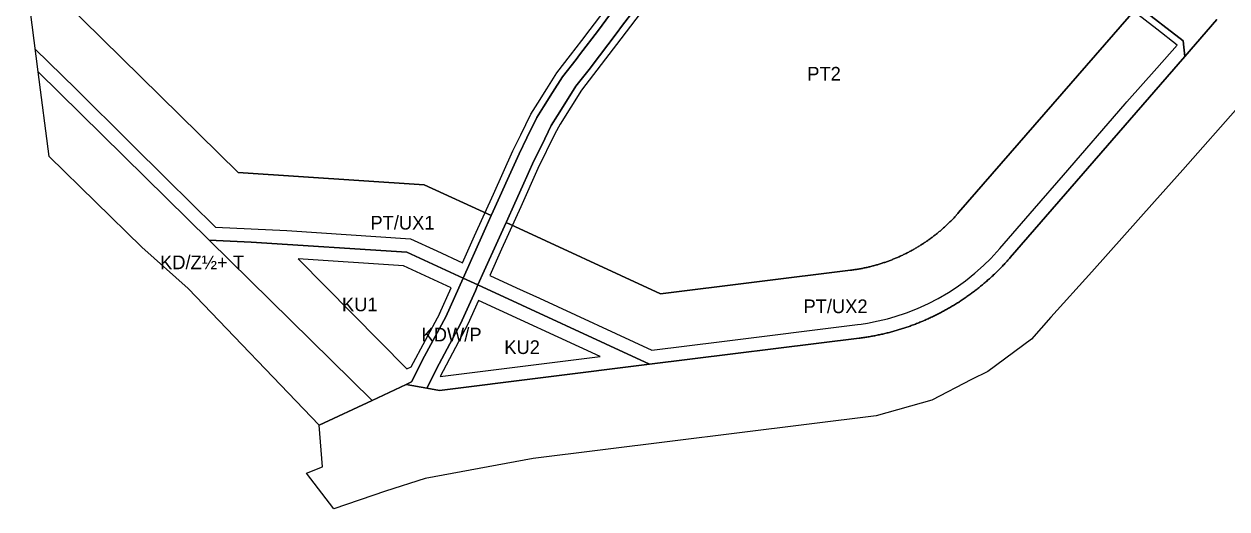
# Model space of a CAD drawing. Extents: x -297746 to -295403, y 27112 to 28877.
# Drawn here: x -297536 to -296657, y 27112 to 27466 of the extents above; entities that cross this region are included whole.
import ezdxf

# ---------------------------------------------------------------- set-up
doc = ezdxf.new("R2010")
doc.units = 0
for name, color, linetype in [('linie_rozgraniczajace', 7, 'Continuous'), ('linie_zabudowy_nieprzekraczalne', 7, 'Continuous'), ('linie_zabudowy_obowiazujace', 7, 'Continuous'), ('oznaczenia_przeznaczen', 7, 'Continuous')]:
    doc.layers.add(name, color=color, linetype=linetype)

msp = doc.modelspace()

# ---------------------------------------------------------------- linework, layer by layer
at = {"layer": 'linie_rozgraniczajace'}
for points in [[(-297194.759, 27325.796), (-297243.742, 27348.41), (-297379.62, 27357.248), (-297536.097, 27511.179)], [(-296721.993, 27478.885), (-296853.18, 27327.985), (-296853.646, 27327.453), (-296854.114, 27326.923), (-296854.585, 27326.396), (-296855.06, 27325.872), (-296855.537, 27325.35), (-296856.018, 27324.831), (-296856.501, 27324.315), (-296856.987, 27323.802), (-296857.476, 27323.291), (-296857.968, 27322.783), (-296858.463, 27322.278), (-296858.96, 27321.776), (-296859.461, 27321.276), (-296859.964, 27320.779), (-296860.47, 27320.285), (-296860.979, 27319.795), (-296861.491, 27319.306), (-296862.005, 27318.821), (-296862.522, 27318.339), (-296863.042, 27317.86), (-296863.565, 27317.383), (-296864.09, 27316.91), (-296864.618, 27316.439), (-296865.148, 27315.972), (-296865.682, 27315.508), (-296866.217, 27315.046), (-296866.756, 27314.588), (-296867.297, 27314.133), (-296867.84, 27313.68), (-296868.386, 27313.231), (-296868.935, 27312.785), (-296869.486, 27312.342), (-296870.04, 27311.902), (-296870.596, 27311.466), (-296871.155, 27311.032), (-296871.716, 27310.602), (-296872.279, 27310.174), (-296872.845, 27309.75), (-296873.413, 27309.33), (-296873.984, 27308.912), (-296874.557, 27308.498), (-296875.132, 27308.087), (-296875.71, 27307.679), (-296876.29, 27307.274), (-296876.872, 27306.873), (-296877.457, 27306.475), (-296878.043, 27306.08), (-296878.632, 27305.689), (-296879.224, 27305.301), (-296879.817, 27304.916), (-296880.412, 27304.535), (-296881.01, 27304.157), (-296881.61, 27303.783), (-296882.212, 27303.412), (-296882.816, 27303.044), (-296883.422, 27302.68), (-296884.03, 27302.319), (-296884.64, 27301.961), (-296885.252, 27301.607), (-296885.866, 27301.257), (-296886.482, 27300.91), (-296887.1, 27300.567), (-296887.72, 27300.227)], [(-296872.279, 27310.174), (-296871.716, 27310.602), (-296871.155, 27311.032), (-296870.596, 27311.466), (-296870.04, 27311.902), (-296869.486, 27312.342), (-296868.935, 27312.785), (-296868.386, 27313.231), (-296867.84, 27313.68), (-296867.297, 27314.133), (-296866.756, 27314.588), (-296866.217, 27315.046), (-296865.682, 27315.508), (-296865.148, 27315.972), (-296864.618, 27316.439), (-296864.09, 27316.91), (-296863.565, 27317.383), (-296863.042, 27317.86), (-296862.522, 27318.339), (-296862.005, 27318.821), (-296861.491, 27319.306), (-296860.979, 27319.795), (-296860.47, 27320.285), (-296859.964, 27320.779), (-296859.461, 27321.276), (-296858.96, 27321.776), (-296858.463, 27322.278), (-296857.968, 27322.783), (-296857.476, 27323.291), (-296856.987, 27323.802), (-296856.501, 27324.315), (-296856.018, 27324.831), (-296855.537, 27325.35), (-296855.06, 27325.872), (-296854.585, 27326.396), (-296854.114, 27326.923), (-296853.646, 27327.453), (-296853.18, 27327.985), (-296721.993, 27478.885), (-296689.133, 27453.416), (-296687.895, 27441.898), (-296815.446, 27295.181), (-296815.997, 27294.551), (-296816.55, 27293.923), (-296817.107, 27293.298), (-296817.666, 27292.676), (-296818.228, 27292.057), (-296818.794, 27291.44), (-296819.362, 27290.826), (-296819.933, 27290.215), (-296820.507, 27289.606), (-296821.084, 27289), (-296821.664, 27288.397), (-296822.247, 27287.797), (-296822.833, 27287.199), (-296823.421, 27286.605), (-296824.013, 27286.013), (-296824.607, 27285.424), (-296825.204, 27284.838), (-296825.803, 27284.254), (-296826.406, 27283.674), (-296827.011, 27283.096), (-296827.619, 27282.522), (-296828.23, 27281.95), (-296828.844, 27281.381), (-296829.46, 27280.815), (-296830.079, 27280.252), (-296830.701, 27279.692), (-296831.325, 27279.135), (-296831.952, 27278.581), (-296832.582, 27278.03), (-296833.214, 27277.482), (-296833.849, 27276.937), (-296834.486, 27276.395), (-296835.126, 27275.857), (-296835.769, 27275.321), (-296836.414, 27274.788), (-296837.062, 27274.258), (-296837.712, 27273.732), (-296838.364, 27273.208), (-296839.02, 27272.688), (-296839.677, 27272.171), (-296840.338, 27271.657), (-296841, 27271.146), (-296841.665, 27270.639), (-296842.333, 27270.134), (-296843.003, 27269.633), (-296843.675, 27269.135), (-296844.349, 27268.64), (-296845.026, 27268.148), (-296845.706, 27267.66), (-296846.387, 27267.175), (-296847.071, 27266.693), (-296847.758, 27266.214), (-296848.446, 27265.739), (-296849.137, 27265.267), (-296849.83, 27264.799), (-296850.525, 27264.333), (-296851.223, 27263.871), (-296851.923, 27263.412)], [(-296664.406, 27468.917), (-296687.895, 27441.898), (-296689.133, 27453.416), (-296721.993, 27478.885)], [(-297204.419, 27275.185), (-297215.315, 27280.215), (-297200.803, 27312.318), (-297194.759, 27325.796), (-297194.532, 27326.301), (-297188.463, 27339.812), (-297182.789, 27352.244), (-297174.341, 27371.048), (-297168.583, 27382.582), (-297161.403, 27397.443), (-297156.407, 27405.272), (-297149.85, 27415.719), (-297142.603, 27427.173), (-297132.752, 27439.87), (-297130.244, 27443.163), (-297116.362, 27461.318), (-297108.268, 27472.193)], [(-297088.887, 27477.865), (-297098.677, 27464.98), (-297103.486, 27458.519), (-297115.701, 27442.453), (-297123.238, 27432.557), (-297132.769, 27420.271), (-297139.698, 27409.321), (-297146.268, 27398.854), (-297150.906, 27391.585), (-297157.812, 27377.292), (-297163.495, 27365.907), (-297171.858, 27347.294), (-297177.532, 27334.862), (-297183.585, 27321.387), (-297183.863, 27320.766), (-297189.862, 27307.391), (-297199.748, 27285.531), (-297204.419, 27275.185)], [(-297071.036, 27268.678), (-297183.863, 27320.766), (-297183.585, 27321.387), (-297177.532, 27334.862), (-297171.858, 27347.294), (-297163.495, 27365.907), (-297157.812, 27377.292), (-297150.906, 27391.585), (-297146.268, 27398.854), (-297139.698, 27409.321), (-297132.769, 27420.271), (-297123.238, 27432.557), (-297115.701, 27442.453), (-297103.486, 27458.519), (-297098.677, 27464.98), (-297088.887, 27477.865)], [(-297108.268, 27472.193), (-297116.362, 27461.318), (-297130.244, 27443.163), (-297132.752, 27439.87), (-297142.603, 27427.173), (-297149.85, 27415.719), (-297156.407, 27405.272), (-297161.403, 27397.443), (-297168.583, 27382.582)], [(-296855.454, 27261.169), (-296854.743, 27261.611), (-296854.035, 27262.056), (-296853.329, 27262.505), (-296852.625, 27262.957), (-296851.923, 27263.412), (-296851.223, 27263.871), (-296850.525, 27264.333), (-296849.83, 27264.799), (-296849.137, 27265.267), (-296848.446, 27265.739), (-296847.758, 27266.214), (-296847.071, 27266.693), (-296846.387, 27267.175), (-296845.706, 27267.66), (-296845.026, 27268.148), (-296844.349, 27268.64), (-296843.675, 27269.135), (-296843.003, 27269.633), (-296842.333, 27270.134), (-296841.665, 27270.639), (-296841, 27271.146), (-296840.338, 27271.657), (-296839.677, 27272.171), (-296839.02, 27272.688), (-296838.364, 27273.208), (-296837.712, 27273.732), (-296837.062, 27274.258), (-296836.414, 27274.788), (-296835.769, 27275.321), (-296835.126, 27275.857), (-296834.486, 27276.395), (-296833.849, 27276.937), (-296833.214, 27277.482), (-296832.582, 27278.03), (-296831.952, 27278.581), (-296831.325, 27279.135), (-296830.701, 27279.692), (-296830.079, 27280.252), (-296829.46, 27280.815), (-296828.844, 27281.381), (-296828.23, 27281.95), (-296827.619, 27282.522), (-296827.011, 27283.096), (-296826.406, 27283.674), (-296825.803, 27284.254), (-296825.204, 27284.838), (-296824.607, 27285.424), (-296824.013, 27286.013), (-296823.421, 27286.605), (-296822.833, 27287.199), (-296822.247, 27287.797), (-296821.664, 27288.397), (-296821.084, 27289), (-296820.507, 27289.606), (-296819.933, 27290.215), (-296819.362, 27290.826), (-296818.794, 27291.44), (-296818.228, 27292.057), (-296817.666, 27292.676), (-296817.107, 27293.298), (-296816.55, 27293.923), (-296815.997, 27294.551), (-296815.446, 27295.181), (-296687.895, 27441.898), (-296664.406, 27468.917)], [(-296647.178, 27406.935), (-296689.426, 27359.239), (-296709.944, 27336.075), (-296755.856, 27284.662), (-296785.648, 27251.677), (-296799.802, 27235.521), (-296831.744, 27212.122), (-296843.745, 27206.187), (-296872.727, 27191.091), (-296913.344, 27179.55), (-297163.969, 27148.392), (-297242.956, 27133.917), (-297271.866, 27124.698), (-297309.67, 27111.664)], [(-297168.583, 27382.582), (-297174.341, 27371.048), (-297182.789, 27352.244), (-297188.463, 27339.812), (-297194.532, 27326.301), (-297194.759, 27325.796)], [(-297079.033, 27217.299), (-297204.419, 27275.185), (-297199.748, 27285.531), (-297189.862, 27307.391), (-297183.863, 27320.766), (-297071.036, 27268.678), (-296932.093, 27285.952), (-296931.877, 27285.979), (-296931.176, 27286.07), (-296930.475, 27286.164), (-296929.775, 27286.262), (-296929.075, 27286.365), (-296928.376, 27286.471), (-296927.678, 27286.581), (-296926.98, 27286.695), (-296926.283, 27286.814), (-296925.586, 27286.936), (-296924.891, 27287.062), (-296924.196, 27287.192), (-296923.501, 27287.326), (-296922.808, 27287.463), (-296922.115, 27287.605), (-296921.423, 27287.751), (-296920.732, 27287.9), (-296920.042, 27288.054), (-296919.352, 27288.211), (-296918.664, 27288.372), (-296917.976, 27288.538), (-296917.29, 27288.707), (-296916.604, 27288.879), (-296915.919, 27289.056), (-296915.236, 27289.237), (-296914.553, 27289.421), (-296913.872, 27289.61), (-296913.191, 27289.802), (-296912.512, 27289.998), (-296911.833, 27290.198), (-296911.156, 27290.402), (-296910.48, 27290.609), (-296909.806, 27290.821), (-296909.132, 27291.036), (-296908.46, 27291.255), (-296907.789, 27291.478), (-296907.119, 27291.705), (-296906.45, 27291.935), (-296905.783, 27292.169), (-296905.117, 27292.407), (-296904.453, 27292.649), (-296903.79, 27292.894), (-296903.128, 27293.144), (-296902.468, 27293.396), (-296901.809, 27293.653), (-296901.151, 27293.914), (-296900.495, 27294.178), (-296899.841, 27294.446), (-296899.188, 27294.717), (-296898.537, 27294.992), (-296897.887, 27295.271), (-296897.239, 27295.554), (-296896.592, 27295.84), (-296895.947, 27296.13), (-296895.304, 27296.423), (-296894.662, 27296.721), (-296894.022, 27297.021), (-296893.384, 27297.326), (-296892.748, 27297.634), (-296892.113, 27297.945), (-296891.48, 27298.261), (-296890.849, 27298.579), (-296890.219, 27298.902), (-296889.592, 27299.228), (-296888.966, 27299.557), (-296888.342, 27299.89), (-296887.72, 27300.227), (-296887.1, 27300.567), (-296886.482, 27300.91), (-296885.866, 27301.257), (-296885.252, 27301.607), (-296884.64, 27301.961), (-296884.03, 27302.319), (-296883.422, 27302.68), (-296882.816, 27303.044), (-296882.212, 27303.412), (-296881.61, 27303.783), (-296881.01, 27304.157), (-296880.412, 27304.535), (-296879.817, 27304.916), (-296879.224, 27305.301), (-296878.632, 27305.689), (-296878.043, 27306.08), (-296877.457, 27306.475), (-296876.872, 27306.873), (-296876.29, 27307.274), (-296875.71, 27307.679), (-296875.132, 27308.087), (-296874.557, 27308.498), (-296873.984, 27308.912), (-296873.413, 27309.33), (-296872.845, 27309.75), (-296872.279, 27310.174)], [(-296887.72, 27300.227), (-296888.342, 27299.89), (-296888.966, 27299.557), (-296889.592, 27299.228), (-296890.219, 27298.902), (-296890.849, 27298.579), (-296891.48, 27298.261), (-296892.113, 27297.945), (-296892.748, 27297.634), (-296893.384, 27297.326), (-296894.022, 27297.021), (-296894.662, 27296.721), (-296895.304, 27296.423), (-296895.947, 27296.13), (-296896.592, 27295.84), (-296897.239, 27295.554), (-296897.887, 27295.271), (-296898.537, 27294.992), (-296899.188, 27294.717), (-296899.841, 27294.446), (-296900.495, 27294.178), (-296901.151, 27293.914), (-296901.809, 27293.653), (-296902.468, 27293.396), (-296903.128, 27293.144), (-296903.79, 27292.894), (-296904.453, 27292.649), (-296905.117, 27292.407), (-296905.783, 27292.169), (-296906.45, 27291.935), (-296907.119, 27291.705), (-296907.789, 27291.478), (-296908.46, 27291.255), (-296909.132, 27291.036), (-296909.806, 27290.821), (-296910.48, 27290.609), (-296911.156, 27290.402), (-296911.833, 27290.198), (-296912.512, 27289.998), (-296913.191, 27289.802), (-296913.872, 27289.61), (-296914.553, 27289.421), (-296915.236, 27289.237), (-296915.919, 27289.056), (-296916.604, 27288.879), (-296917.29, 27288.707), (-296917.976, 27288.538), (-296918.664, 27288.372), (-296919.352, 27288.211), (-296920.042, 27288.054), (-296920.732, 27287.9), (-296921.423, 27287.751), (-296922.115, 27287.605), (-296922.808, 27287.463), (-296923.501, 27287.326), (-296924.196, 27287.192), (-296924.891, 27287.062), (-296925.586, 27286.936), (-296926.283, 27286.814), (-296926.98, 27286.695), (-296927.678, 27286.581), (-296928.376, 27286.471), (-296929.075, 27286.365), (-296929.775, 27286.262), (-296930.475, 27286.164), (-296931.176, 27286.07), (-296931.877, 27285.979), (-296932.093, 27285.952), (-297071.036, 27268.678)], [(-297309.67, 27111.664), (-297329.685, 27137.732), (-297317.93, 27142.501), (-297320.472, 27172.702), (-297281.793, 27190.875), (-297256.857, 27202.591), (-297241.827, 27199.879), (-297232.578, 27198.21), (-297079.033, 27217.299), (-296925.925, 27236.334), (-296925.095, 27236.439), (-296924.266, 27236.548), (-296923.437, 27236.662), (-296922.608, 27236.779), (-296921.781, 27236.9), (-296920.953, 27237.025), (-296920.127, 27237.154), (-296919.301, 27237.287), (-296918.475, 27237.423), (-296917.651, 27237.564), (-296916.826, 27237.709), (-296916.003, 27237.858), (-296915.181, 27238.01), (-296914.359, 27238.167), (-296913.538, 27238.327), (-296912.717, 27238.492), (-296911.898, 27238.66), (-296911.079, 27238.832), (-296910.261, 27239.008), (-296909.444, 27239.189), (-296908.628, 27239.373), (-296907.812, 27239.56), (-296906.998, 27239.752), (-296906.185, 27239.948), (-296905.372, 27240.147), (-296904.561, 27240.351), (-296903.75, 27240.558), (-296902.94, 27240.769), (-296902.132, 27240.984), (-296901.324, 27241.203), (-296900.518, 27241.426), (-296899.712, 27241.653), (-296898.908, 27241.883), (-296898.105, 27242.117), (-296897.303, 27242.355), (-296896.502, 27242.597), (-296895.702, 27242.843), (-296894.904, 27243.093), (-296894.106, 27243.346), (-296893.31, 27243.604), (-296892.515, 27243.865), (-296891.722, 27244.129), (-296890.929, 27244.398), (-296890.138, 27244.671), (-296889.349, 27244.947), (-296888.56, 27245.227), (-296887.773, 27245.51), (-296886.987, 27245.798), (-296886.203, 27246.089), (-296885.42, 27246.384), (-296884.639, 27246.683), (-296883.859, 27246.985), (-296883.08, 27247.292), (-296882.303, 27247.602), (-296881.527, 27247.915), (-296880.753, 27248.232), (-296879.98, 27248.553), (-296879.209, 27248.878), (-296878.44, 27249.207), (-296877.672, 27249.539), (-296876.905, 27249.874), (-296876.141, 27250.214), (-296875.378, 27250.557), (-296874.616, 27250.904), (-296873.856, 27251.254), (-296873.098, 27251.608), (-296872.342, 27251.966), (-296871.587, 27252.327), (-296870.834, 27252.692), (-296870.083, 27253.06), (-296869.334, 27253.432), (-296868.586, 27253.807), (-296867.84, 27254.187), (-296867.096, 27254.569), (-296866.354, 27254.956), (-296865.614, 27255.345), (-296864.875, 27255.739), (-296864.139, 27256.136), (-296863.404, 27256.536), (-296862.671, 27256.94), (-296861.941, 27257.347), (-296861.212, 27257.758), (-296860.485, 27258.172), (-296859.76, 27258.59), (-296859.037, 27259.011), (-296858.316, 27259.436), (-296857.598, 27259.864), (-296856.881, 27260.296), (-296856.166, 27260.731), (-296855.454, 27261.169)], [(-296851.923, 27263.412), (-296852.625, 27262.957), (-296853.329, 27262.505), (-296854.035, 27262.056), (-296854.743, 27261.611), (-296855.454, 27261.169), (-296856.166, 27260.731), (-296856.881, 27260.296), (-296857.598, 27259.864), (-296858.316, 27259.436), (-296859.037, 27259.011), (-296859.76, 27258.59), (-296860.485, 27258.172), (-296861.212, 27257.758), (-296861.941, 27257.347), (-296862.671, 27256.94), (-296863.404, 27256.536), (-296864.139, 27256.136), (-296864.875, 27255.739), (-296865.614, 27255.345), (-296866.354, 27254.956), (-296867.096, 27254.569), (-296867.84, 27254.187), (-296868.586, 27253.807), (-296869.334, 27253.432), (-296870.083, 27253.06), (-296870.834, 27252.692), (-296871.587, 27252.327), (-296872.342, 27251.966), (-296873.098, 27251.608), (-296873.856, 27251.254), (-296874.616, 27250.904), (-296875.378, 27250.557), (-296876.141, 27250.214), (-296876.905, 27249.874), (-296877.672, 27249.539), (-296878.44, 27249.207), (-296879.209, 27248.878), (-296879.98, 27248.553), (-296880.753, 27248.232), (-296881.527, 27247.915), (-296882.303, 27247.602), (-296883.08, 27247.292), (-296883.859, 27246.985), (-296884.639, 27246.683), (-296885.42, 27246.384), (-296886.203, 27246.089), (-296886.987, 27245.798), (-296887.773, 27245.51), (-296888.56, 27245.227), (-296889.349, 27244.947), (-296890.138, 27244.671), (-296890.929, 27244.398), (-296891.722, 27244.129), (-296892.515, 27243.865), (-296893.31, 27243.604), (-296894.106, 27243.346), (-296894.904, 27243.093), (-296895.702, 27242.843), (-296896.502, 27242.597), (-296897.303, 27242.355), (-296898.105, 27242.117), (-296898.908, 27241.883), (-296899.712, 27241.653), (-296900.518, 27241.426), (-296901.324, 27241.203), (-296902.132, 27240.984), (-296902.94, 27240.769), (-296903.75, 27240.558), (-296904.561, 27240.351), (-296905.372, 27240.147), (-296906.185, 27239.948), (-296906.998, 27239.752), (-296907.812, 27239.56), (-296908.628, 27239.373), (-296909.444, 27239.189), (-296910.261, 27239.008), (-296911.079, 27238.832), (-296911.898, 27238.66), (-296912.717, 27238.492), (-296913.538, 27238.327), (-296914.359, 27238.167), (-296915.181, 27238.01), (-296916.003, 27237.858), (-296916.826, 27237.709), (-296917.651, 27237.564), (-296918.475, 27237.423), (-296919.301, 27237.287), (-296920.127, 27237.154), (-296920.953, 27237.025), (-296921.781, 27236.9), (-296922.608, 27236.779), (-296923.437, 27236.662), (-296924.266, 27236.548), (-296925.095, 27236.439), (-296925.925, 27236.334), (-297079.033, 27217.299)]]:
    msp.add_lwpolyline(points, dxfattribs=at)
for points in [[(-297215.315, 27280.215), (-297256.262, 27299.118), (-297370.123, 27306.524), (-297400.878, 27308.022), (-297525.782, 27430.894), (-297536.097, 27511.179), (-297379.62, 27357.248), (-297243.742, 27348.41), (-297194.759, 27325.796), (-297200.803, 27312.318)], [(-297320.472, 27172.702), (-297416.254, 27272.62), (-297449.929, 27302.821), (-297517.834, 27369.03), (-297525.782, 27430.894), (-297400.878, 27308.022), (-297281.793, 27190.875)], [(-297281.793, 27190.875), (-297400.878, 27308.022), (-297370.123, 27306.524), (-297256.262, 27299.118), (-297215.315, 27280.215), (-297227.961, 27251.981), (-297243.361, 27223.14), (-297252.992, 27204.408), (-297256.857, 27202.591)], [(-297241.827, 27199.879), (-297256.857, 27202.591), (-297252.992, 27204.408), (-297243.361, 27223.14), (-297227.961, 27251.981), (-297215.315, 27280.215), (-297204.419, 27275.185), (-297206.313, 27270.99), (-297217.178, 27246.699), (-297232.732, 27217.57)], [(-297232.578, 27198.21), (-297241.827, 27199.879), (-297232.732, 27217.57), (-297217.178, 27246.699), (-297206.313, 27270.99), (-297204.419, 27275.185), (-297079.033, 27217.299)]]:
    msp.add_lwpolyline(points, close=True, dxfattribs=at)
at = {"layer": 'linie_zabudowy_nieprzekraczalne'}
for points in [[(-297215.732, 27291.425), (-297206.81, 27311.187), (-297193.099, 27341.555), (-297193.104, 27341.557), (-297178.857, 27373.192), (-297173.068, 27384.788), (-297165.774, 27399.886), (-297160.629, 27407.947), (-297154.077, 27418.387), (-297146.697, 27430.051), (-297136.713, 27442.92), (-297128.473, 27453.74), (-297122.317, 27461.69), (-297112.261, 27475.2), (-297100.171, 27490.416), (-297097.508, 27493.578), (-297053.016, 27545.96)], [(-297072.903, 27489.098), (-297081.873, 27478.434), (-297100.081, 27454.794), (-297128.669, 27417.398), (-297144.393, 27392.527), (-297148.27, 27385.544), (-297160.613, 27360.118), (-297173.096, 27332.32), (-297187.105, 27301.347), (-297195.763, 27282.206)], [(-296708.266, 27433.526), (-296693.334, 27450.351), (-296708.383, 27462.014)], [(-296797.697, 27330.904), (-296776.579, 27355.249)], [(-297253.176, 27215.37), (-297232.368, 27254.338), (-297232.521, 27254.027), (-297223.939, 27273.186), (-297258.762, 27289.262), (-297335.819, 27294.274)], [(-297335.819, 27294.274), (-297256.434, 27213.839), (-297253.176, 27215.37)], [(-297115.023, 27222.903), (-297203.974, 27263.968), (-297211.773, 27246.531), (-297231.978, 27208.363)]]:
    msp.add_lwpolyline(points, dxfattribs=at)
at = {"layer": 'linie_zabudowy_obowiazujace'}
for points in [[(-296708.383, 27462.014), (-296737.15, 27484.311)], [(-297527.88, 27447.247), (-297498.376, 27418.349), (-297458.675, 27378.912), (-297431.879, 27352.551), (-297396.235, 27317.487), (-297344.077, 27314.854), (-297253.755, 27308.979), (-297234.442, 27300.063), (-297215.732, 27291.425)], [(-296776.579, 27355.249), (-296731.452, 27407.404), (-296730.124, 27408.9), (-296708.266, 27433.526)], [(-297195.763, 27282.206), (-297176.156, 27273.154), (-297159.445, 27265.439), (-297077.431, 27227.577), (-297026.298, 27233.934), (-296927.155, 27246.26), (-296924.391, 27246.627), (-296919.722, 27247.356), (-296911.84, 27248.901), (-296905.164, 27250.526), (-296899.596, 27252.11), (-296891.328, 27254.86), (-296883.315, 27258), (-296875.189, 27261.694), (-296868.157, 27265.335), (-296860.539, 27269.782), (-296854.925, 27273.425), (-296848.184, 27278.246), (-296841.261, 27283.762), (-296834.929, 27289.376), (-296829.699, 27294.478), (-296822.99, 27301.744), (-296797.697, 27330.904)], [(-297231.978, 27208.363), (-297115.023, 27222.903)]]:
    msp.add_lwpolyline(points, dxfattribs=at)

# ---------------------------------------------------------------- texts
at = {"layer": 'oznaczenia_przeznaczen'}
for s, p in [('PT2', (-296963.754, 27424.422)), ('PT/UX1', (-297282.996, 27315.635)), ('KD/Z½+ T', (-297436.713, 27286.707)), ('KU1', (-297303.764, 27255.991)), ('PT/UX2', (-296966.491, 27254.602)), ('KDW/P', (-297245.602, 27233.991)), ('KU2', (-297185.152, 27224.765))]:
    msp.add_text(s, height=10, dxfattribs=at).set_placement(p)

doc.saveas('drawing.dxf')
